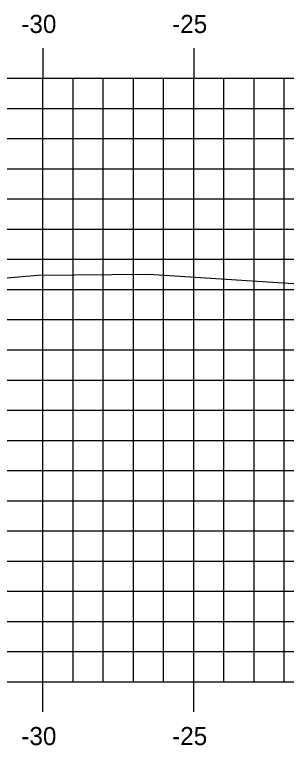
# Model space of a CAD drawing. Extents: x -161 to 764, y 111 to 210.
# Drawn here: x 379.66 to 388.66, y 174.14 to 198.36 of the extents above; entities that cross this region are included whole.
import ezdxf

# ---------------------------------------------------------------- set-up
doc = ezdxf.new("R2010")
doc.units = 0
for name, color, linetype in [('H_V ANNOTATION', 7, 'Continuous'), ('MAJOR', 7, 'Continuous'), ('MINOR', 7, 'Continuous'), ('S_Roadway_Centerline', 7, 'Continuous')]:
    doc.layers.add(name, color=color, linetype=linetype)

msp = doc.modelspace()

# ---------------------------------------------------------------- linework, layer by layer
at = {"layer": 'MAJOR'}
for p, q in [((380.591, 197.249), (380.591, 196.247)), ((385.591, 197.249), (385.591, 196.247)), ((340.591, 196.247), (480.591, 196.247)), ((340.591, 196.247), (480.591, 196.247)), ((380.591, 176.247), (380.591, 196.247)), ((385.591, 176.247), (385.591, 196.247)), ((340.591, 191.247), (480.591, 191.247)), ((340.591, 186.247), (480.591, 186.247)), ((340.591, 181.247), (480.591, 181.247)), ((340.591, 176.247), (480.591, 176.247)), ((340.591, 176.247), (480.591, 176.247)), ((380.591, 175.245), (380.591, 176.247)), ((385.591, 175.245), (385.591, 176.247))]:
    msp.add_line(p, q, dxfattribs=at)
at = {"layer": 'MINOR'}
for p, q in [((381.591, 176.247), (381.591, 196.247)), ((382.591, 176.247), (382.591, 196.247)), ((383.591, 176.247), (383.591, 196.247)), ((384.591, 176.247), (384.591, 196.247)), ((386.591, 176.247), (386.591, 196.247)), ((387.591, 176.247), (387.591, 196.247)), ((388.591, 176.247), (388.591, 196.247)), ((340.591, 195.247), (480.591, 195.247)), ((340.591, 194.247), (480.591, 194.247)), ((340.591, 193.247), (480.591, 193.247)), ((340.591, 192.247), (480.591, 192.247)), ((340.591, 190.247), (480.591, 190.247)), ((340.591, 189.247), (480.591, 189.247)), ((340.591, 188.247), (480.591, 188.247)), ((340.591, 187.247), (480.591, 187.247)), ((340.591, 185.247), (480.591, 185.247)), ((340.591, 184.247), (480.591, 184.247)), ((340.591, 183.247), (480.591, 183.247)), ((340.591, 182.247), (480.591, 182.247)), ((340.591, 180.247), (480.591, 180.247)), ((340.591, 179.247), (480.591, 179.247)), ((340.591, 178.247), (480.591, 178.247)), ((340.591, 177.247), (480.591, 177.247))]:
    msp.add_line(p, q, dxfattribs=at)
at = {"layer": 'S_Roadway_Centerline'}
msp.add_lwpolyline([(340.591, 183.558), (346.27, 184.146), (348.315, 184.806), (354.074, 186.337), (357.168, 187.075), (364.507, 188.564), (366.124, 189.037), (373.039, 189.084), (380.424, 189.717), (384.106, 189.757), (390.092, 189.37), (397.718, 189.529), (407.599, 189.997), (414.618, 189.716), (422.879, 189.785), (430.793, 190.018)], dxfattribs=at)

# ---------------------------------------------------------------- texts
at = {"layer": 'H_V ANNOTATION'}
for s, p in [('-30', (379.879, 197.747)), ('-25', (384.876, 197.747)), ('-30', (379.879, 174.147)), ('-25', (384.876, 174.147))]:
    msp.add_text(s, height=0.6, rotation=360, dxfattribs=at).set_placement(p)

doc.saveas('drawing.dxf')
